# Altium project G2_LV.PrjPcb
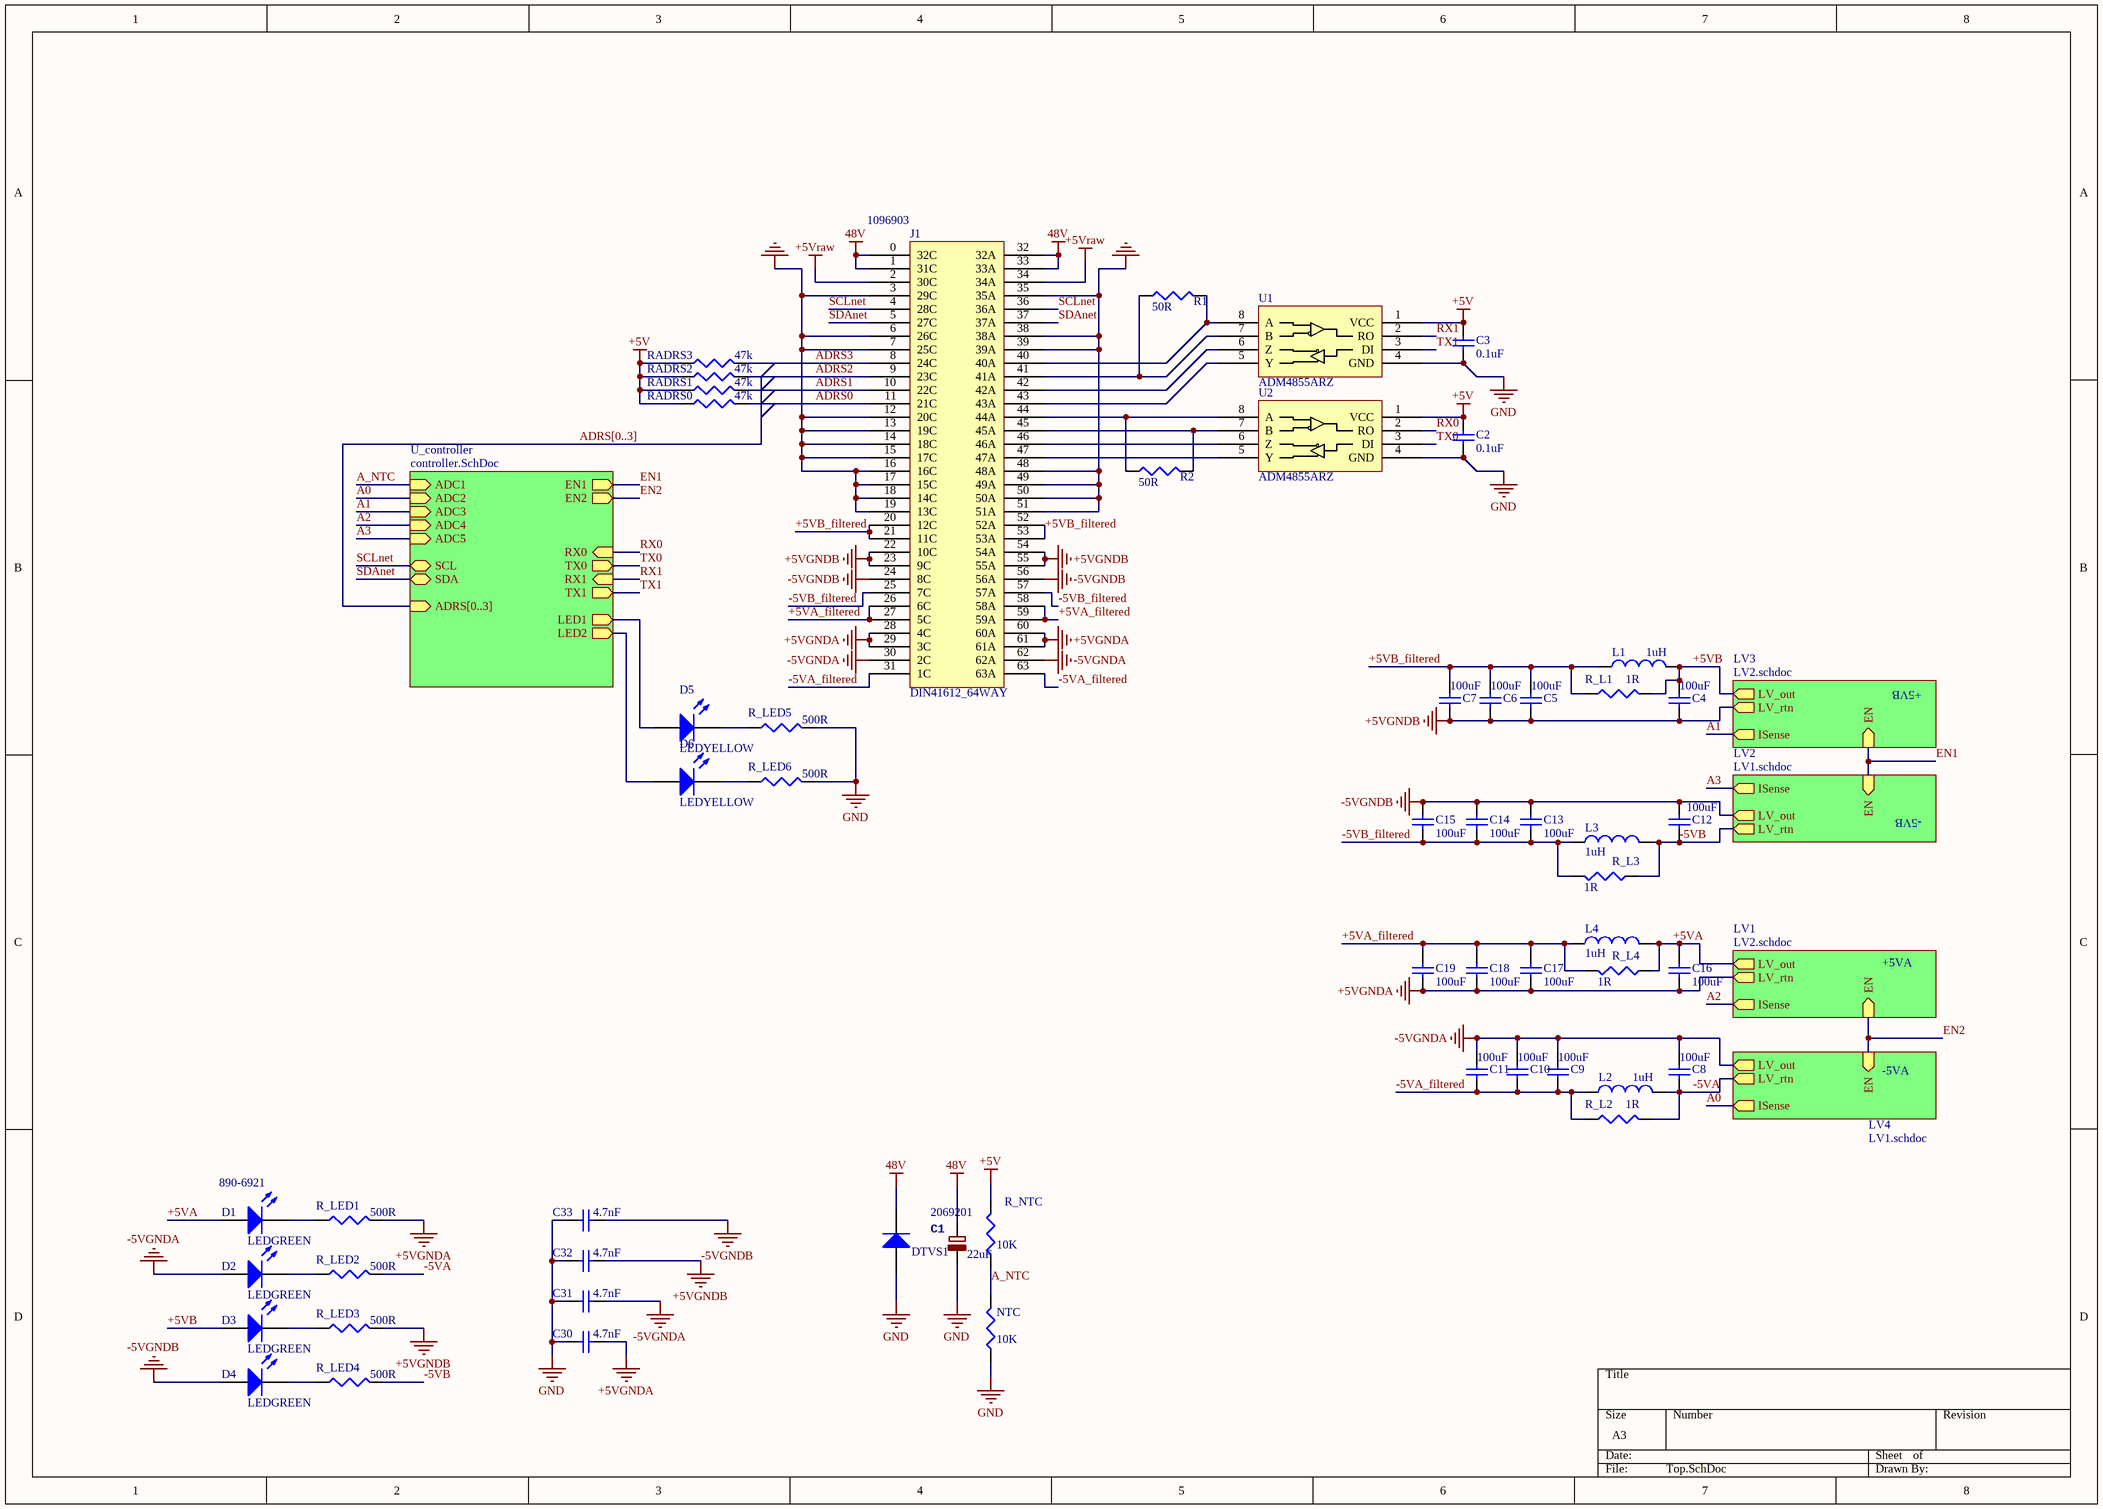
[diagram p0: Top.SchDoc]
4 sheets, 185 parts. Net scope: hierarchical (ports join the sheet entries above them; power ports are global).
Board files: 6C-2L-1550um.PcbDoc, LV1.PCBDOC
Sheets:
  Top.SchDoc
    LV3 = LV2.schdoc
    LV1 = LV2.schdoc
    LV2 = LV1.schdoc
    LV4 = LV1.schdoc
    U_controller = controller.SchDoc

## Sheet Top.SchDoc
size A3

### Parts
C1  value 22uF  Supplier Part Number 1: 2069201  [PANASONIC_D]
C2  value 0.1uF  [1608[0603]]  (hidden comment: Cap Semi)
C3  value 0.1uF  [1608[0603]]  (hidden comment: Cap Semi)
C4  value 100uF  [C1210]  (hidden comment: Cap Semi)
C5  value 100uF  [C1210]  (hidden comment: Cap Semi)
C6  value 100uF  [C1210]  (hidden comment: Cap Semi)
C7  value 100uF  [C1210]  (hidden comment: Cap Semi)
C8  value 100uF  [C1210]  (hidden comment: Cap Semi)
C9  value 100uF  [C1210]  (hidden comment: Cap Semi)
C10  value 100uF  [C1210]  (hidden comment: Cap Semi)
C11  value 100uF  [C1210]  (hidden comment: Cap Semi)
C12  value 100uF  [C1210]  (hidden comment: Cap Semi)
C13  value 100uF  [C1210]  (hidden comment: Cap Semi)
C14  value 100uF  [C1210]  (hidden comment: Cap Semi)
C15  value 100uF  [C1210]  (hidden comment: Cap Semi)
C16  value 100uF  [C1210]  (hidden comment: Cap Semi)
C17  value 100uF  [C1210]  (hidden comment: Cap Semi)
C18  value 100uF  [C1210]  (hidden comment: Cap Semi)
C19  value 100uF  [C1210]  (hidden comment: Cap Semi)
C30  value 4.7nF  [1812]  (hidden comment: Cap Semi)
C31  value 4.7nF  [1812]  (hidden comment: Cap Semi)
C32  value 4.7nF  [1812]  (hidden comment: Cap Semi)
C33  value 4.7nF  [1812]  (hidden comment: Cap Semi)
D1  LEDGREEN  Supplier Part Number 1: 890-6921  [LEDGREEN]
D2  LEDGREEN  [LEDGREEN]
D3  LEDGREEN  [LEDGREEN]
D4  LEDGREEN  [LEDGREEN]
D5  LEDYELLOW  [LEDYELLOW]
D6  LEDYELLOW  [LEDYELLOW]
DTVS1  SMBJ48A  [DO-214AA]  (value not drawn)
J1  DIN41612_64WAY  Supplier Part Number 1: 1096903  [09 03 164 6919]
L1  value 1uH  [MPLC0730]  (hidden comment: Inductor)
L2  value 1uH  [MPLC0730]  (hidden comment: Inductor)
L3  value 1uH  [MPLC0730]  (hidden comment: Inductor)
L4  value 1uH  [MPLC0730]  (hidden comment: Inductor)
NTC  value 10K  [J1-0603]
R1  value 50R  [J1-0603]
R2  value 50R  [J1-0603]
R_L1  value 1R  [J1-0603]  (hidden comment: Res3)
R_L2  value 1R  [J1-0603]  (hidden comment: Res3)
R_L3  value 1R  [J1-0603]  (hidden comment: Res3)
R_L4  value 1R  [J1-0603]  (hidden comment: Res3)
R_LED1  value 500R  [J1-0603]  (hidden comment: Res3)
R_LED2  value 500R  [J1-0603]  (hidden comment: Res3)
R_LED3  value 500R  [J1-0603]  (hidden comment: Res3)
R_LED4  value 500R  [J1-0603]  (hidden comment: Res3)
R_LED5  value 500R  [J1-0603]  (hidden comment: Res3)
R_LED6  value 500R  [J1-0603]  (hidden comment: Res3)
R_NTC  value 10K  [J1-0603]
RADRS0  value 47k  [J1-0603]  (hidden comment: Res3)
RADRS1  value 47k  [J1-0603]  (hidden comment: Res3)
RADRS2  value 47k  [J1-0603]  (hidden comment: Res3)
RADRS3  value 47k  [J1-0603]  (hidden comment: Res3)
U1  ADM4855ARZ  [SOICN8]
U2  ADM4855ARZ  [SOICN8]

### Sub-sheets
LV1 = LV2.schdoc: ISense (out), EN (in), LV_out (out), LV_rtn (out)
LV2 = LV1.schdoc: LV_out (out), LV_rtn (out), EN (in), ISense (out)
LV3 = LV2.schdoc: ISense (out), EN (in), LV_out (out), LV_rtn (out)
LV4 = LV1.schdoc: LV_out (out), LV_rtn (out), EN (in), ISense (out)
U_controller = controller.SchDoc: EN1 (out), ADC1 (in), ADC2 (in), EN2 (out), ADC3 (in), ADC4 (in), SCL (bidir), SDA (bidir), RX0 (in), TX0 (out), RX1 (in), TX1 (out), ADC5 (in), LED1 (out), LED2 (out), ADRS[0..3] (in)

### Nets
48V: C1.1 DTVS1.1(K) J1.0(32C) J1.1(31C) J1.32(32A) J1.33(33A)
+5V: C2.2 C3.2 R_NTC.2 RADRS0.1 RADRS1.1 RADRS2.1 RADRS3.1 U1.1(VCC) U2.1(VCC)
+5VGNDA: C16.2 C17.2 C18.2 C19.2 C30.2 J1.28(4C) J1.29(3C) J1.60(60A) J1.61(61A) R_LED1.2 ; sheet LV1/LV_rtn
+5VGNDB: C4.1 C5.1 C6.1 C7.1 C32.2 J1.22(10C) J1.23(9C) J1.54(54A) J1.55(55A) R_LED3.2 ; sheet LV3/LV_rtn
+5Vraw: J1.2(30C) J1.34(34A)
-5VGNDA: C8.2 C9.2 C10.2 C11.2 C31.2 D2.2(A) J1.30(2C) J1.62(62A) ; sheet LV4/LV_out
-5VGNDB: C12.1 C13.1 C14.1 C15.1 C33.2 D4.2(A) J1.24(8C) J1.56(56A) ; sheet LV2/LV_out
GND: C1.2 C2.1 C3.1 C30.1 C31.1 C32.1 C33.1 DTVS1.2(A) J1.3(29C) J1.6(26C) J1.7(25C) J1.12(20C) J1.13(19C) J1.14(18C) J1.15(17C) J1.16(16C) J1.17(15C) J1.18(14C) J1.19(13C) J1.35(35A) J1.38(38A) J1.39(39A) J1.48(48A) J1.49(49A) J1.50(50A) J1.51(51A) NTC.1 R_LED5.2 R_LED6.2 U1.4(GND) U2.4(GND)
+5VA: C16.1 D1.2(A) L4.2 R_L4.1 ; sheet LV1/LV_out
+5VA_filtered: C17.1 C18.1 C19.1 J1.26(6C) J1.27(5C) J1.58(58A) J1.59(59A) L4.1 R_L4.2
+5VB: C4.2 D3.2(A) L1.2 R_L1.2 ; sheet LV3/LV_out
+5VB_filtered: C5.2 C6.2 C7.2 J1.20(12C) J1.21(11C) J1.52(52A) J1.53(53A) L1.1 R_L1.1
-5VA: C8.1 L2.2 R_L2.2 R_LED2.2 ; sheet LV4/LV_rtn
-5VA_filtered: C9.1 C10.1 C11.1 J1.31(1C) J1.63(63A) L2.1 R_L2.1
-5VB: C12.2 L3.2 R_L3.1 R_LED4.2 ; sheet LV2/LV_rtn
-5VB_filtered: C13.2 C14.2 C15.2 J1.25(7C) J1.57(57A) L3.1 R_L3.2
A0: sheet LV4/ISense, sheet U_controller/ADC2
A1: sheet LV3/ISense, sheet U_controller/ADC3
A2: sheet LV1/ISense, sheet U_controller/ADC4
A3: sheet LV2/ISense, sheet U_controller/ADC5
A_NTC: NTC.2 R_NTC.1 ; sheet U_controller/ADC1
ADRS0: J1.11(21C) RADRS0.2
ADRS1: J1.10(22C) RADRS1.2
ADRS2: J1.9(23C) RADRS2.2
ADRS3: J1.8(24C) RADRS3.2
EN1: sheet LV3/EN, sheet LV2/EN, sheet U_controller/EN1
EN2: sheet LV1/EN, sheet LV4/EN, sheet U_controller/EN2
RX0: U2.2(RO) ; sheet U_controller/RX0
RX1: U1.2(RO) ; sheet U_controller/RX1
SCLnet: J1.4(28C) J1.36(36A) ; sheet U_controller/SCL  [project net SCL]
SDAnet: J1.5(27C) J1.37(37A) ; sheet U_controller/SDA  [project net SDA]
TX0: U2.3(DI) ; sheet U_controller/TX0
TX1: U1.3(DI) ; sheet U_controller/TX1
NetD1_1: D1.1(K) R_LED1.1
NetD2_1: D2.1(K) R_LED2.1
NetD3_1: D3.1(K) R_LED3.1
NetD4_1: D4.1(K) R_LED4.1
NetD5_1: D5.1(K) R_LED5.1
NetD5_2: D5.2(A) ; sheet U_controller/LED1
NetD6_1: D6.1(K) R_LED6.1
NetD6_2: D6.2(A) ; sheet U_controller/LED2
NetJ1_40: J1.40(40A) R1.2 U1.8(A)
NetJ1_41: J1.41(41A) R1.1 U1.7(B)
NetJ1_42: J1.42(42A) U1.6(Z)
NetJ1_43: J1.43(43A) U1.5(Y)
NetJ1_44: J1.44(44A) R2.1 U2.8(A)
NetJ1_45: J1.45(45A) R2.2 U2.7(B)
NetJ1_46: J1.46(46A) U2.6(Z)
NetJ1_47: J1.47(47A) U2.5(Y)

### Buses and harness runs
bus ADRS[0..3] = sheet U_controller/ADRS[0..3]

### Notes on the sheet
- +5VB
- -5VB
- +5VA
- -5VA

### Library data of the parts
C1 = CPOL-EUD: PartNo: EMZA500ADA220MF61G
C2 C3 = Cap Semi: Capacitor (Semiconductor SIM Model); PartNo: CC0603KRX7R9BB104
C4 C8 C12 C16 = Cap Semi: Capacitor (Semiconductor SIM Model); PartNo: C3225X5R0J107M250AC
C5-C7 C9-C11 C13-C15 C17-C19 = Cap Semi: Capacitor (Semiconductor SIM Model); PartNo: CL32A107MPVNNNE
C30-C33 = Cap Semi: Capacitor (Semiconductor SIM Model); PartNo: C1812C472KDRACTU
D1-D4 = LEDGREEN: PartNo: 550-0207F
D5 D6 = LEDYELLOW: PartNo: 550-0307F
DTVS1 = SMBJ: TVS; Note: Pin 2 is not connected and not drawn.
J1 = DIN41612_64WAY: PartNo: 0903 164 6921
L1-L4 = Inductor: PartNo: MPLC0730L1R0; Code_IEC: 1005
NTC = Res3: Resistor; PartNo: NCP18XH103J03RB
R1 R2 R_L1-R_L4 R_LED1-R_LED6 R_NTC RADRS0-RADRS3 = Res3: Resistor
U1 U2 = SP3084EEN-L

## Sheet LV2.schdoc
size A4
Used 2 times, as channels LV3, LV1. Parts and nets are listed once, with the designators drawn on the sheet.
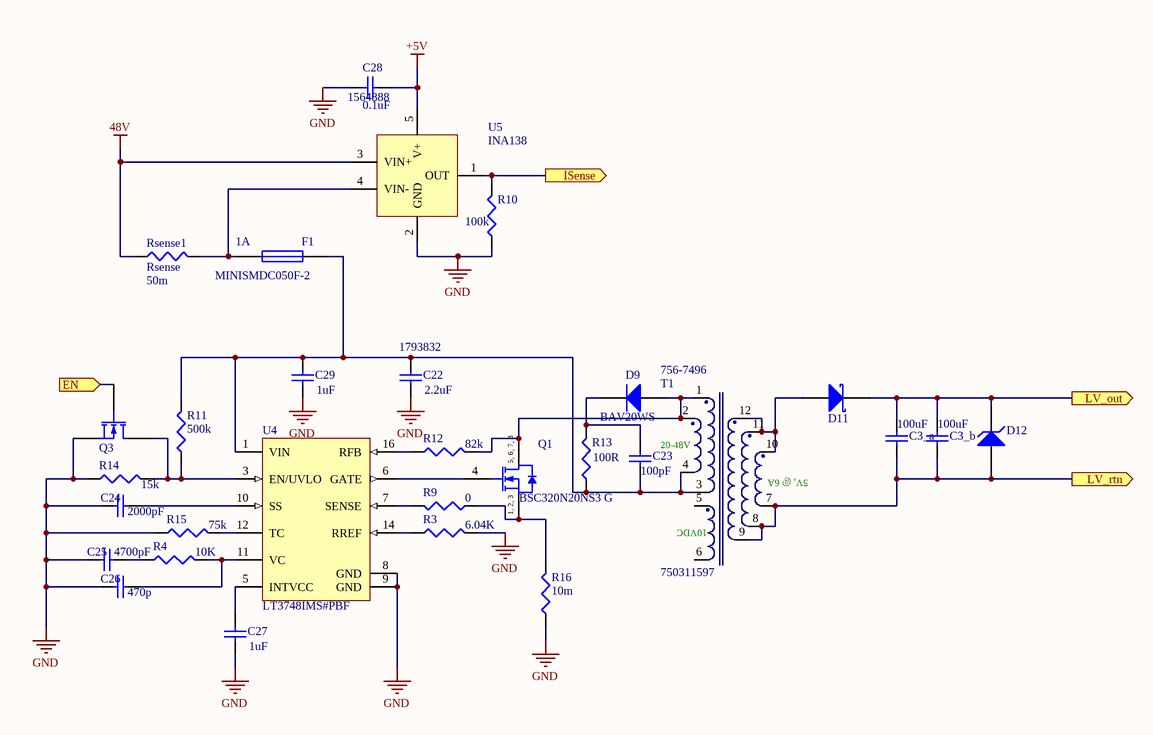
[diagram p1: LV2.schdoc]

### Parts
C3_a  value 100uF  [C1210]  (hidden comment: Cap Semi)
C3_b  value 100uF  [C1210]  (hidden comment: Cap Semi)
C22  value 2.2uF  Supplier Part Number 1: 1793832  [C1210]  (hidden comment: Cap Semi)
C23  value 100pF  [C0805]  (hidden comment: Cap Semi)
C24  value 2000pF  [0402]  (hidden comment: Cap Semi)
C25  value 4700pF  [0402]  (hidden comment: Cap Semi)
C26  value 470p  [0402]  (hidden comment: Cap Semi)
C27  value 1uF  [C0805]  (hidden comment: Cap Semi)
C28  value 0.1uF  [1608[0603]]  (hidden comment: Cap Semi)
C29  value 1uF  [C0805]  (hidden comment: Cap Semi)
D9  BAV20WS  [SOD-323]
D11  PDS760-13  [PDS1040L]  (value not drawn)
D12  BZT52H-B5V6  [SOD123F]  (value not drawn)
F1  MINISMDC050F-2  Tripping current: 1A  [MF-MSMF1]
Q1  BSC320N20NS3 G  [INF-PG-TDSON-8-1_V]
Q3  BSS131  [SOT-23_2]  (value not drawn)
R3  value 6.04K  [J1-0603]  (hidden comment: Res3)
R4  value 10K  [J1-0603]  (hidden comment: Res3)
R9  value 0  [J1-0603]  (hidden comment: Res3)
R10  value 100k  [J1-0603]  (hidden comment: Res3)
R11  value 500k  [J1-0603]  (hidden comment: Res3)
R12  value 82k  [J1-0603]  (hidden comment: Res3)
R13  value 100R  [C1206]  (hidden comment: Res3)
R14  value 15k  [J1-0603]  (hidden comment: Res3)
R15  value 75k  [J1-0603]  (hidden comment: Res3)
R16  value 10m  [C1206]  (hidden comment: Res3)
Rsense1  Rsense  value 50m  [R6432]
T1  750311597  Supplier Part Number 1: 756-7496  [EFD20]
U4  LT3748IMS#PBF  [LT-MS-16-4PR_N]
U5  INA138  Supplier Part Number 1: 1564888  [SOT-23]

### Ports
EN (in), ISense (out), LV_out (out), LV_rtn (out)

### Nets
48V: Rsense1.1 U5.3(VIN+)
+5V: C28.2 U5.5(V+)
GND: C22.1 C24.1 C25.1 C26.1 C27.1 C28.1 C29.1 Q3.2(S) R3.2 R10.1 R14.1 R15.1 R16.1 U4.8(GND) U4.9(GND) U5.2(GND)
EN: Q3.1(G) ; port EN
ISense: R10.2 U5.1(OUT) ; port ISense
LV_out: C3_a.2 C3_b.2 D11.2(K) D12.2(K) ; port LV_out
LV_rtn: C3_a.1 C3_b.1 D12.1(A) T1.7 T1.8 T1.9 ; port LV_rtn
NetC22_2: C22.2 C23.2 C29.2 F1.2 R11.2 R13.1 T1.3 T1.4 U4.1(VIN)
NetC23_1: C23.1 D9.1(K) R13.2
NetC24_2: C24.2 U4.10(SS)
NetC25_2: C25.2 R4.1
NetC26_2: C26.2 R4.2 U4.11(VC)
NetC27_2: C27.2 U4.5(INTVCC)
NetD9_2: D9.2(A) Q1.5(DRAIN) Q1.6(DRAIN) Q1.7(DRAIN) Q1.8(DRAIN) R12.2 T1.1 T1.2
NetD11_1: D11.1(A) T1.10 T1.11 T1.12
NetF1_1: F1.1 Rsense1.2 U5.4(VIN-)
NetQ1_1: Q1.1(SOURCE) Q1.2(SOURCE) Q1.3(SOURCE) R9.1 R16.2
NetQ1_4: Q1.4(GATE) U4.6(GATE)
NetQ3_3: Q3.3(D) R11.1 R14.2 U4.3(EN/UVLO)
NetR3_1: R3.1 U4.14(RREF)
NetR9_2: R9.2 U4.7(SENSE)
NetR12_1: R12.1 U4.16(RFB)
NetR15_2: R15.2 U4.12(TC)

Not connected (* = marked no-connect by the designer): T1 5 6

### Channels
LV3: designators end in _LV3; ports EN=EN1 ISense=A1 LV_out=+5VB LV_rtn=+5VGNDB
LV1: designators end in _LV1; ports EN=EN2 ISense=A2 LV_out=+5VA LV_rtn=+5VGNDA

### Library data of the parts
C3_a C3_b = Cap Semi: as C4 on sheet Top
C22 = Cap Semi: Capacitor (Semiconductor SIM Model); PartNo: C1210C225K1RACTU
C23 = Cap Semi: Capacitor (Semiconductor SIM Model); PartNo: 08055A221JAT2A
C24 C29 = Cap Semi: Capacitor (Semiconductor SIM Model)
C25 = Cap Semi: Capacitor (Semiconductor SIM Model); PartNo: 04025C472KAT2A
C26 = Cap Semi: Capacitor (Semiconductor SIM Model); PartNo: C1005C0G1H471J050BA
C27 = Cap Semi: Capacitor (Semiconductor SIM Model); PartNo: MC0805F105Z500CT
C28 = Cap Semi: as C2 on sheet Top
D9 = BAV20WS: Power Diode; Note: Pin 2 is not connected and not drawn.
D11 = PDS1040L: Schottky Diode
D12 = BZT52H-B5V6: Zener Diode; pin to pad: 1>2 2>1
F1 = Fuse 1: Fuse
Q1 = BSC320N20NS3 G: N-Channel OptiMOS 3 Power-Transistor, 200 V VDS, 36 A ID, -55 to 150 degC, PG-TDSON-8-1, Reel, Green; Manufacturer: Infineon; Green: TRUE; ID (max): 36 A; IDpuls (max): 144 A; Polarity: N; Ptot (max): 125 W; QG: 22 nC; RDS (on) (max): 32 mOhm; Rth: 1 K/W; RthJA (max): 1.5 K/W; RthJC (max): 62 K/W; VDS (max): 200 V; VGS(th) (max): 4 V; VGS(th) (min): 2 V
Q3 = BSS131: N-Channel MOSFET
R3 R4 R9-R15 = Res3: Resistor
R16 = Res3: Resistor; PartNo: LRMAM1206-R01FT5
Rsense1 = Rsense: CRF2512-FV-R001ELF; PartNo: MCS3264R050FER
T1 = 750311597: Flyback Transformer suitable or LT3573/ LT3574/ LT3575/ LT3748 WE-FB, Ui=20-48V; Ui: 20-48V
U4 = LT3748IMS#PBF: Isolated Flyback Controller, 16-pin SOP (MS-16), -40 to 125 degC, Pb-Free; Manufacturer: Linear Technology; Number of Outputs: 1
U5 = INA138: PartNo: INA138NA/250

## Sheet LV1.schdoc: Eurocard VME 3U (3.937 x 6.299 inches)
size A; Organization: Organization; Address1: Address1; Address2: Address2; Address3: Address3; Address4: Address4; DocumentNumber: 1; Revision: 0; SheetNumber: 2; SheetTotal: 2
Used 2 times, as channels LV2, LV4. Parts and nets are listed once, with the designators drawn on the sheet.
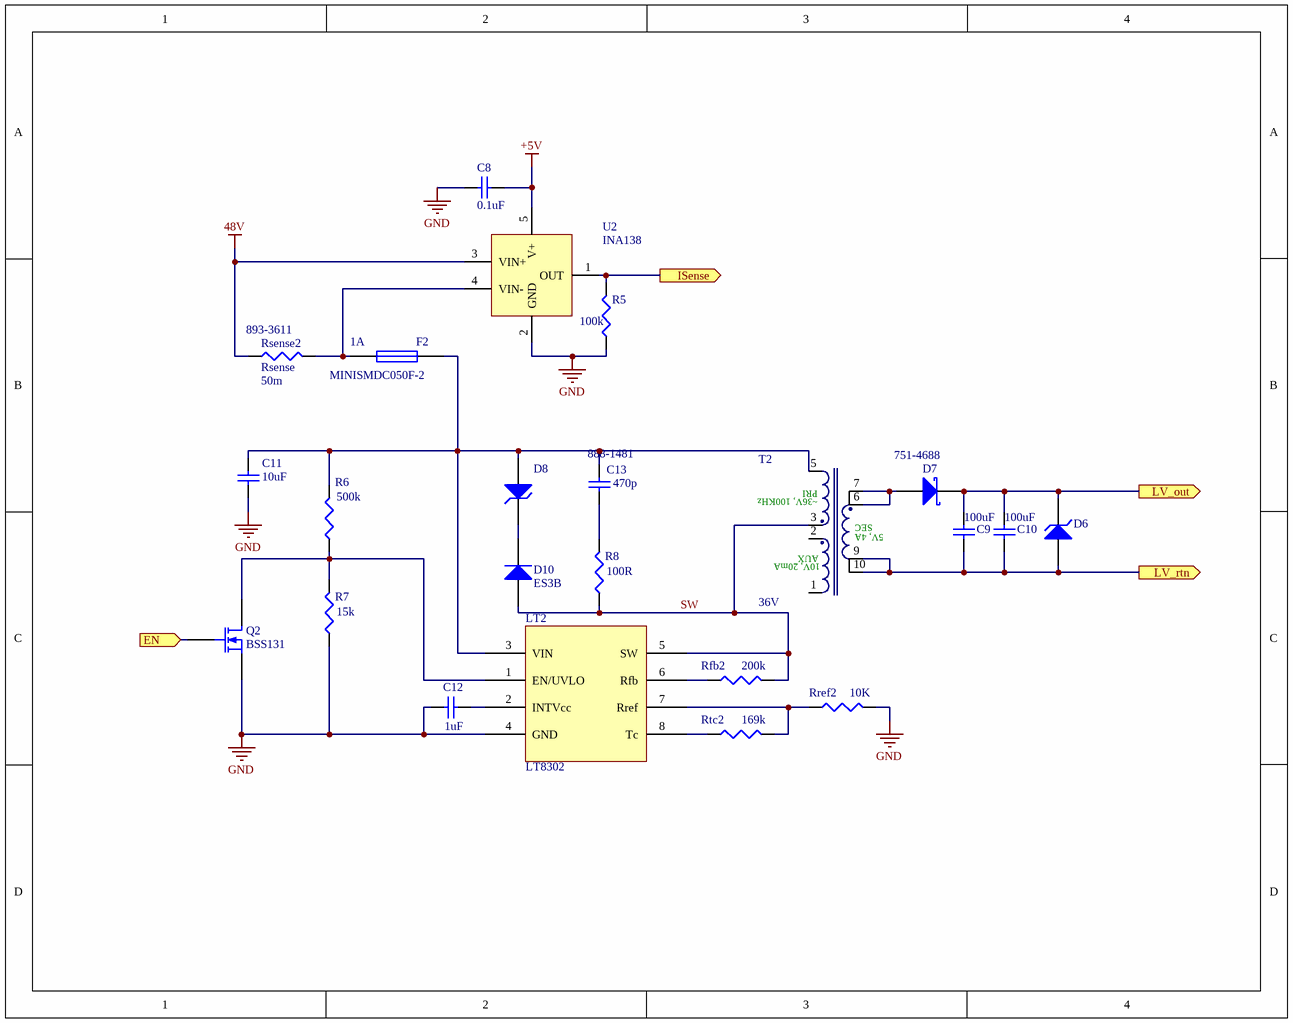
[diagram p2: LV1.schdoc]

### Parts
C8  value 0.1uF  [1608[0603]]  (hidden comment: Cap Semi)
C9  value 100uF  [C1210]  (hidden comment: Cap Semi)
C10  value 100uF  [C1210]  (hidden comment: Cap Semi)
C11  value 10uF  [C1210]  (hidden comment: Cap Semi)
C12  value 1uF  [1608[0603]]  (hidden comment: Cap Semi)
C13  value 470p  Supplier Part Number 1: 888-1481  [C0805]  (hidden comment: Cap Semi)
D6  BZT52H-B5V6  [SOD123F]  (value not drawn)
D7  Supplier Part Number 1: 751-4688  [PDS1040L]  (hidden comment: PDS1040L)
D8  SMAJ30A  [DO-214AC]  (value not drawn)
D10  ES3B  [DO-214AB]
F2  MINISMDC050F-2  Tripping current: 1A  [MF-MSMF1]
LT2  LT8302  [S8E]
Q2  BSS131  [SOT-23_2]
R5  value 100k  [J1-0603]  (hidden comment: Res3)
R6  value 500k  [J1-0603]  (hidden comment: Res3)
R7  value 15k  [J1-0603]  (hidden comment: Res3)
R8  value 100R  [C1206]  (hidden comment: Res3)
Rfb2  value 200k  [J1-0603]  (hidden comment: Res3)
Rref2  value 10K  [J1-0603]  (hidden comment: Res3)
Rsense2  Rsense  value 50m  Supplier Part Number 1: 893-3611  [R6432]
Rtc2  value 169k  [J1-0603]  (hidden comment: Res3)
T2  36V  [EP13]
U2  INA138  [SOT-23]

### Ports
EN (in), ISense (out), LV_out (out), LV_rtn (out)

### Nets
48V: Rsense2.1 U2.3(VIN+)
+5V: C8.2 U2.5(V+)
GND: C8.1 C11.1 C12.2 LT2.4(GND) Q2.2(S) R5.1 R7.1 Rref2.2 U2.2(GND)
EN: Q2.1(G) ; port EN
ISense: R5.2 U2.1(OUT) ; port ISense
LV_out: C9.2 C10.2 D6.2(K) D7.2(K) ; port LV_out
LV_rtn: C9.1 C10.1 D6.1(A) T2.9 T2.10 ; port LV_rtn
SW: D10.2(A) LT2.5(SW) R8.1 Rfb2.2 T2.3
NetC11_2: C11.2 C13.2 D8.1(A) F2.2 LT2.3(VIN) R6.2 T2.5
NetC12_1: C12.1 LT2.2(INTVcc)
NetC13_1: C13.1 R8.2
NetD7_1: D7.1(A) T2.6 T2.7
NetD8_2: D8.2(K) D10.1(K)
NetF2_1: F2.1 Rsense2.2 U2.4(VIN-)
NetLT2_1: LT2.1(EN/UVLO) Q2.3(D) R6.1 R7.2
NetLT2_6: LT2.6(Rfb) Rfb2.1
NetLT2_7: LT2.7(Rref) Rref2.1 Rtc2.2
NetLT2_8: LT2.8(Tc) Rtc2.1

Not connected (* = marked no-connect by the designer): T2 1 2

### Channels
LV2: designators end in _LV2; ports EN=EN1 ISense=A3 LV_out=-5VGNDB LV_rtn=-5VB
LV4: designators end in _LV4; ports EN=EN2 ISense=A0 LV_out=-5VGNDA LV_rtn=-5VA

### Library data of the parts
C8 = Cap Semi: as C2 on sheet Top
C9 C10 = Cap Semi: as C4 on sheet Top
C11 = Cap Semi: Capacitor (Semiconductor SIM Model); PartNo: UMK325BJ106KM-T
C12 = Cap Semi: Capacitor (Semiconductor SIM Model); PartNo: 06033D105KAT2A
C13 = Cap Semi: as C23 on sheet LV2
D6 = BZT52H-B5V6: Zener Diode; pin to pad: 1>2 2>1
D7 = PDS1040L: Schottky Diode; PartNo: PDS760-13
D8 = D Zener: Zener Diode
D10 = ES3B: Power Diode; Note: Pin 2 is not connected and not drawn.
F2 = Fuse 1: Fuse
LT2 = LT8302: PartNo: LT8302ES8E#PBF
Q2 = BSS131: N-Channel MOSFET
R5-R8 Rfb2 Rref2 Rtc2 = Res3: Resistor
Rsense2 = Rsense: as Rsense1 on sheet LV2
T2 = WE-FB, 750311457: Flyback Transformer suitable or LT3573/ LT3574/ LT3575/ LT3748 WE-FB, Ui=36V; Manufacturer: Würth Elektronik eiSos GmbH
U2 = INA138: PartNo: INA138NA/250

## Sheet controller.SchDoc
size A3
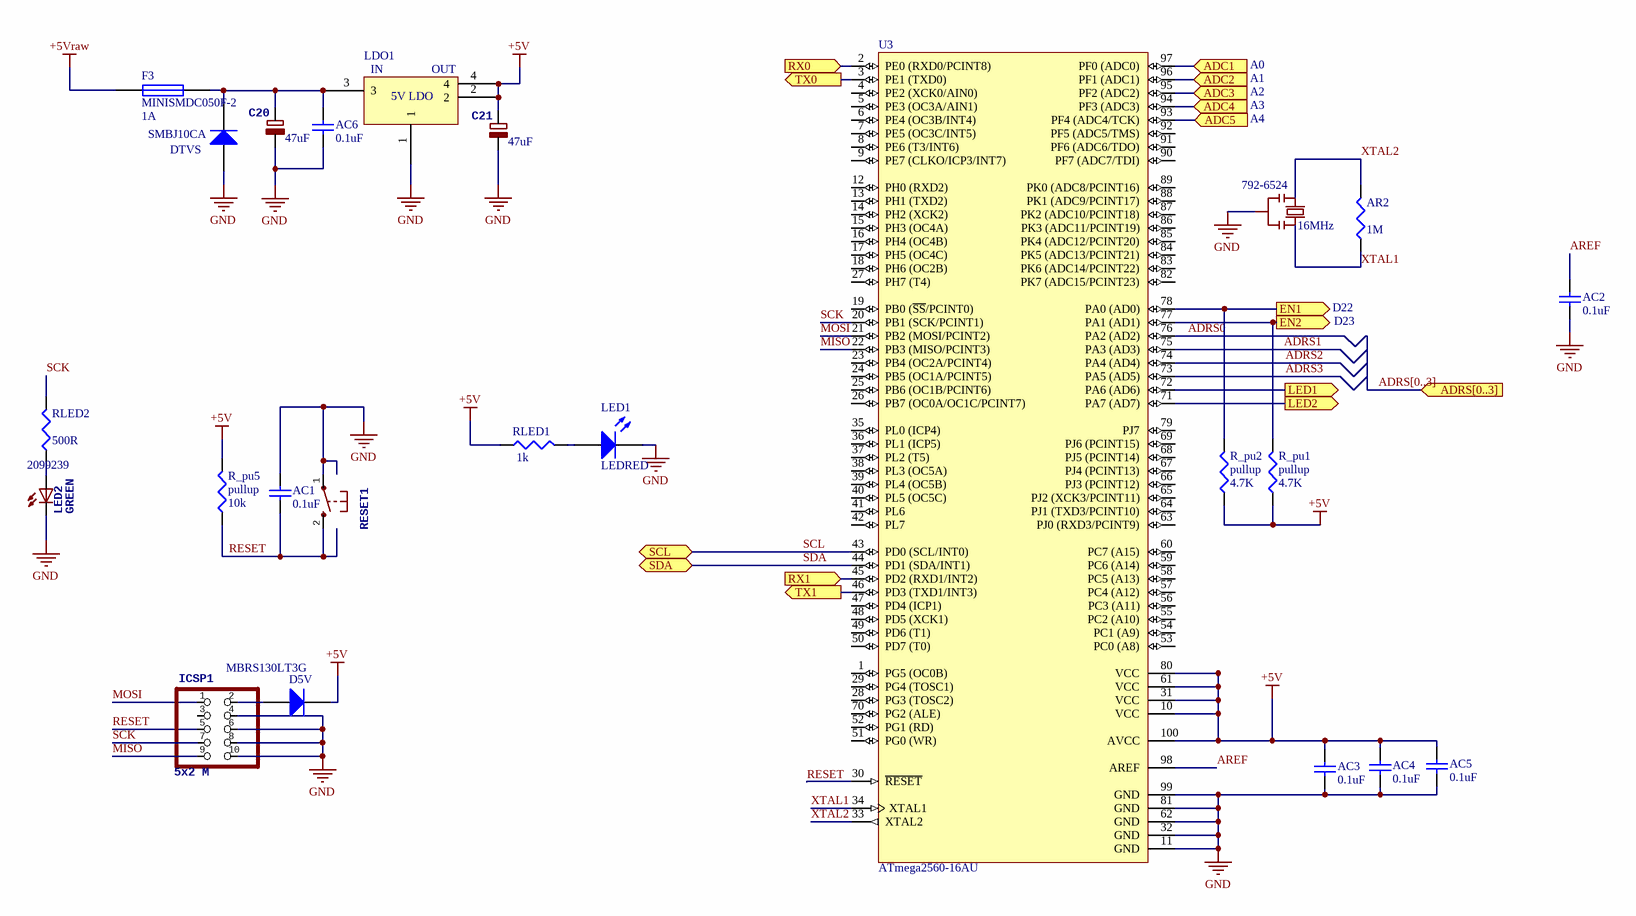
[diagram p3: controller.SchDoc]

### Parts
AC1  value 0.1uF  [1608[0603]]  (hidden comment: Cap Semi)
AC2  value 0.1uF  [1608[0603]]  (hidden comment: Cap Semi)
AC3  value 0.1uF  [1608[0603]]  (hidden comment: Cap Semi)
AC4  value 0.1uF  [1608[0603]]  (hidden comment: Cap Semi)
AC5  value 0.1uF  [1608[0603]]  (hidden comment: Cap Semi)
AC6  value 0.1uF  [1608[0603]]  (hidden comment: Cap Semi)
AR2  value 1M  [J1-0603]
C20  value 47uF  [PANASONIC_D]
C21  value 47uF  [PANASONIC_D]
D5V  MBRS130LT3G  [SMB-403A]
DTVS  SMBJ10CA  [DO-214AA]
F3  MINISMDC050F-2  Tripping current: 1A  [MF-MSMF1]
ICSP1  5x2 M  [2X05]
LDO1  LDO_5V  [SOT223]  (value not drawn)
LED1  LEDRED  [LEDRED]
LED2  GREEN  Supplier Part Number 1: 2099239  [CHIP-LED0805]
R_pu1  pullup  value 4.7K  [J1-0603]
R_pu2  pullup  value 4.7K  [J1-0603]
R_pu5  pullup  value 10k  [J1-0603]
RESET1  PB_RST  [1-1825027-4]  (value not drawn)
RLED1  value 1k  [J1-0603]
RLED2  value 500R  [J1-0603]
U3  ATmega2560-16AU  [100A_N]
Y1  Supplier Part Number 1: 792-6524  [RESONATOR]

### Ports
ADC1 (in), ADC2 (in), ADC3 (in), ADC4 (in), ADC5 (in), ADRS[0..3] (in), EN1 (out), EN2 (out), LED1 (out), LED2 (out), RX0 (in), RX1 (in), SCL (bidir), SDA (bidir), TX0 (out), TX1 (out)

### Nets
+5V: AC3.2 AC4.2 AC5.2 C21.1 D5V.1(K) LDO1.2 LDO1.4 R_pu1.1 R_pu2.1 R_pu5.2 RLED1.1 U3.10(VCC) U3.31(VCC) U3.61(VCC) U3.80(VCC) U3.100(AVCC)
+5Vraw: F3.1
GND: AC1.2 AC2.1 AC3.1 AC4.1 AC5.1 AC6.1 C20.2 C21.2 DTVS.2(A) ICSP1.4 ICSP1.6 ICSP1.8 ICSP1.10 LDO1.1 LED1.1(K) LED2.C RESET1.1 U3.11(GND) U3.32(GND) U3.62(GND) U3.81(GND) U3.99(GND) Y1.2
A0: U3.96(PF1_(ADC1)) ; port ADC2
A1: U3.95(PF2_(ADC2)) ; port ADC3
A2: U3.94(PF3_(ADC3)) ; port ADC4
A3: U3.93(PF4_(ADC4/TCK)) ; port ADC5
A_NTC: U3.97(PF0_(ADC0)) ; port ADC1
ADRS0: U3.76(PA2_(AD2))
ADRS1: U3.75(PA3_(AD3))
ADRS2: U3.74(PA4_(AD4))
ADRS3: U3.73(PA5_(AD5))
AREF: AC2.2 U3.98(AREF)
EN1: R_pu2.2 U3.78(PA0_(AD0)) ; port EN1
EN2: R_pu1.2 U3.77(PA1_(AD1)) ; port EN2
MISO: ICSP1.9 U3.22(PB3_(MISO/PCINT3))
MOSI: ICSP1.1 U3.21(PB2_(MOSI/PCINT2))
RESET: AC1.1 ICSP1.5 R_pu5.1 RESET1.2 U3.30(~{RESET})
RX0: U3.2(PE0_(RXD0/PCINT8)) ; port RX0
RX1: U3.45(PD2_(RXD1/INT2)) ; port RX1
SCK: ICSP1.7 RLED2.2 U3.20(PB1_(SCK/PCINT1))
SCL: U3.43(PD0_(SCL/INT0)) ; port SCL
SDA: U3.44(PD1_(SDA/INT1)) ; port SDA
TX0: U3.3(PE1_(TXD0)) ; port TX0
TX1: U3.46(PD3_(TXD1/INT3)) ; port TX1
XTAL1: AR2.1 U3.34(XTAL1) Y1.3
XTAL2: AR2.2 U3.33(XTAL2) Y1.1
NetAC6_2: AC6.2 C20.1 DTVS.1(K) F3.2 LDO1.3
NetD5_2: U3.72(PA6_(AD6)) ; port LED1
NetD5V_2: D5V.2(A) ICSP1.2
NetD6_2: U3.71(PA7_(AD7)) ; port LED2
NetLED1_2: LED1.2(A) RLED1.2
NetLED2_A: LED2.A RLED2.1

Not connected (* = marked no-connect by the designer): ICSP1 3; U3 1(PG5_(OC0B)) 4(PE2_(XCK0/AIN0)) 5(PE3_(OC3A/AIN1)) 6(PE4_(OC3B/INT4)) 7(PE5_(OC3C/INT5)) 8(PE6_(T3/INT6)) 9(PE7_(CLKO/ICP3/INT7)) 12(PH0_(RXD2)) 13(PH1_(TXD2)) 14(PH2_(XCK2)) 15(PH3_(OC4A)) 16(PH4_(OC4B)) 17(PH5_(OC4C)) 18(PH6_(OC2B)) 19(PB0_(~{SS}/PCINT0)) 23(PB4_(OC2A/PCINT4)) 24(PB5_(OC1A/PCINT5)) 25(PB6_(OC1B/PCINT6)) 26(PB7_(OC0A/OC1C/PCINT7)) 27(PH7_(T4)) 28(PG3_(TOSC2)) 29(PG4_(TOSC1)) 35(PL0_(ICP4)) 36(PL1_(ICP5)) 37(PL2_(T5)) 38(PL3_(OC5A)) 39(PL4_(OC5B)) 40(PL5_(OC5C)) 41(PL6) 42(PL7) 47(PD4_(ICP1)) 48(PD5_(XCK1)) 49(PD6_(T1)) 50(PD7_(T0)) 51(PG0_(WR)) 52(PG1_(RD)) 53(PC0_(A8)) 54(PC1_(A9)) 55(PC2_(A10)) 56(PC3_(A11)) 57(PC4_(A12)) 58(PC5_(A13)) 59(PC6_(A14)) 60(PC7_(A15)) 63(PJ0_(RXD3/PCINT9)) 64(PJ1_(TXD3/PCINT10)) 65(PJ2_(XCK3/PCINT11)) 66(PJ3_(PCINT12)) 67(PJ4_(PCINT13)) 68(PJ5_(PCINT14)) 69(PJ6_(PCINT15)) 70(PG2_(ALE)) 79(PJ7) 82(PK7_(ADC15/PCINT23)) 83(PK6_(ADC14/PCINT22)) 84(PK5_(ADC13/PCINT21)) 85(PK4_(ADC12/PCINT20)) 86(PK3_(ADC11/PCINT19)) 87(PK2_(ADC10/PCINT18)) 88(PK1_(ADC9/PCINT17)) 89(PK0_(ADC8/PCINT16)) 90(PF7_(ADC7/TDI)) 91(PF6_(ADC6/TDO)) 92(PF5_(ADC5/TMS))

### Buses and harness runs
bus ADRS[0..3] = port ADRS[0..3]

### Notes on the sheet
- A0
- A1
- A2
- A3
- A4
- (near Y1) 16MHz
- D22
- D23

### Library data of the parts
AC1-AC6 = Cap Semi: as C2 on sheet Top
AR2 R_pu1 R_pu2 R_pu5 RLED1 RLED2 = Res3: Resistor
C20 C21 = CPOL-EUD: PartNo: EEE1EA470WAP
D5V = MBRS130LT3G: Power Diode; Note: Pin 2 is not connected and not drawn.
DTVS = SMBJ: as DTVS1 on sheet Top
F3 = Fuse 1: Fuse
ICSP1 = PINHD-2X5: PartNo: 2-1761605-3
LDO1 = LDO_5V: PartNo: NCP1117ST50T3G
LED1 = LEDRED: PartNo: 550-0407F
LED2 = LEDCHIP-LED0805: PartNo: KPT-2012SGC
U3 = ATmega2560-16AU: 8-bit AVR Microcontroller, 4.5-5.5V, 16MHz, 256KB Flash, 4KB EEPROM, 8KB SRAM, 86 GPIO pins, 100-pin TQFP, Industrial Grade (-40°C to 85°C), Pb-Free
Y1 = RESONATORMU: PartNo: CSTCE16M0V53-R0

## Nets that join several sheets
48V: Top (6 pins), LV3 (Rsense1_LV3.1 U5_LV3.3), LV1 (Rsense1_LV1.1 U5_LV1.3), LV2 (Rsense2_LV2.1 U2_LV2.3), LV4 (Rsense2_LV4.1 U2_LV4.3)
+5V: Top (9 pins), LV3 (C28_LV3.2 U5_LV3.5), LV1 (C28_LV1.2 U5_LV1.5), LV2 (C8_LV2.2 U2_LV2.5), LV4 (C8_LV4.2 U2_LV4.5), controller (16 pins)
+5VGNDA: Top (10 pins), LV1 (6 pins)
+5VGNDB: Top (10 pins), LV3 (6 pins)
+5Vraw: Top (J1.2 J1.34), controller (F3.1)
-5VGNDA: Top (8 pins), LV4 (C9_LV4.2 C10_LV4.2 D6_LV4.2 D7_LV4.2)
-5VGNDB: Top (8 pins), LV2 (C9_LV2.2 C10_LV2.2 D6_LV2.2 D7_LV2.2)
GND: Top (31 pins), LV3 (16 pins), LV1 (16 pins), LV2 (9 pins), LV4 (9 pins), controller (23 pins)
+5VA: Top (C16.1 D1.2 L4.2 R_L4.1), LV1 (C3_a_LV1.2 C3_b_LV1.2 D11_LV1.2 D12_LV1.2)
+5VB: Top (C4.2 D3.2 L1.2 R_L1.2), LV3 (C3_a_LV3.2 C3_b_LV3.2 D11_LV3.2 D12_LV3.2)
-5VA: Top (C8.1 L2.2 R_L2.2 R_LED2.2), LV4 (5 pins)
-5VB: Top (C12.2 L3.2 R_L3.1 R_LED4.2), LV2 (5 pins)
A0: LV4 (R5_LV4.2 U2_LV4.1), controller (U3.96)
A1: LV3 (R10_LV3.2 U5_LV3.1), controller (U3.95)
A2: LV1 (R10_LV1.2 U5_LV1.1), controller (U3.94)
A3: LV2 (R5_LV2.2 U2_LV2.1), controller (U3.93)
A_NTC: Top (NTC.2 R_NTC.1), controller (U3.97)
ADRS0: Top (J1.11 RADRS0.2), controller (U3.76)
ADRS1: Top (J1.10 RADRS1.2), controller (U3.75)
ADRS2: Top (J1.9 RADRS2.2), controller (U3.74)
ADRS3: Top (J1.8 RADRS3.2), controller (U3.73)
EN1: LV3 (Q3_LV3.1), LV2 (Q2_LV2.1), controller (R_pu2.2 U3.78)
EN2: LV1 (Q3_LV1.1), LV4 (Q2_LV4.1), controller (R_pu1.2 U3.77)
NetD5_2: Top (D5.2), controller (U3.72)
NetD6_2: Top (D6.2), controller (U3.71)
RX0: Top (U2.2), controller (U3.2)
RX1: Top (U1.2), controller (U3.45)
SCL: Top (J1.4 J1.36), controller (U3.43)
SDA: Top (J1.5 J1.37), controller (U3.44)
TX0: Top (U2.3), controller (U3.3)
TX1: Top (U1.3), controller (U3.46)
